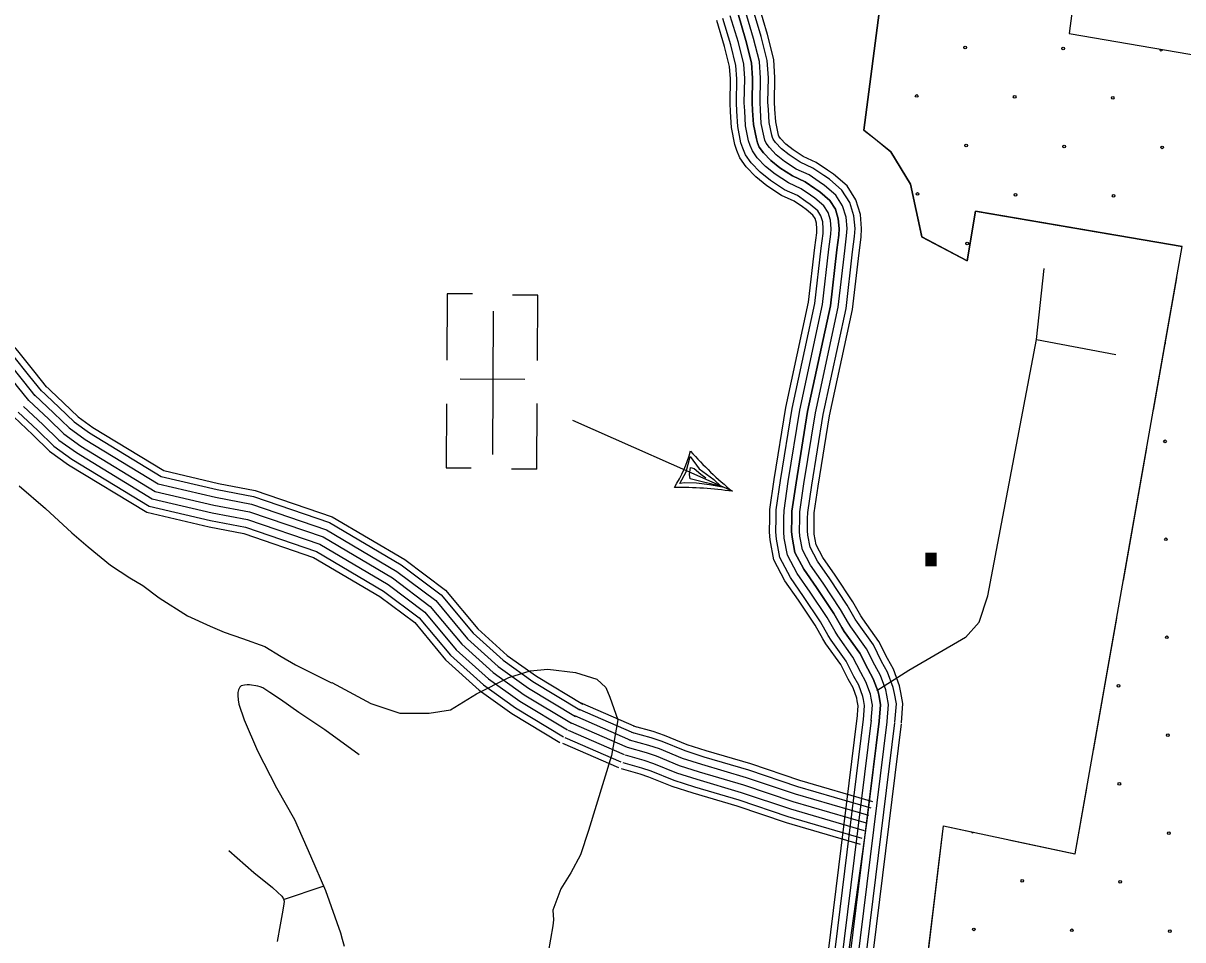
# Model space of a CAD drawing. Extents: x 1788175 to 1969470, y 584502 to 738744.
# Drawn here: x 1805045 to 1809595, y 690385 to 693983 of the extents above; entities that cross this region are included whole.
import ezdxf

# ---------------------------------------------------------------- set-up
doc = ezdxf.new("R2010")
doc.units = 0
for name, color, linetype in [('DESIGN - EROSION CONTROL - Devices', 7, 'Continuous'), ('DESIGN - SCRATCH - User 1', 7, 'Continuous'), ('DESIGN - TRANSPORTATION - Text', 7, 'Continuous'), ('DESIGN - UTILITIES - Cable (Overhead) with Text', 7, 'Continuous'), ('DESIGN - UTILITIES - Cable (Underground) with Text', 7, 'Continuous'), ('SURVEY - CONTOURS - Intermediate with optional Text', 7, 'Continuous'), ('SURVEY - TRANSPORTATION - Roads', 7, 'Continuous'), ('SURVEY - VEGETATION - Features with Text', 7, 'Continuous')]:
    doc.layers.add(name, color=color, linetype=linetype)

msp = doc.modelspace()

# ---------------------------------------------------------------- linework, layer by layer
at = {"layer": 'DESIGN - EROSION CONTROL - Devices'}
for centre in [(1808740.7, 693887.4), (1809125.2, 693883.7), (1808550.3, 693697), (1808934.8, 693693.3), (1809319.4, 693689.5), (1808744.4, 693502.9), (1809129, 693499.1), (1809513.5, 693495.4), (1808554, 693312.5), (1808938.5, 693308.7), (1809323.1, 693305), (1808748.1, 693118.3), (1809524.7, 692341.7), (1809528.4, 691957.2), (1809532.2, 691572.6), (1809341.8, 691382.2), (1809535.9, 691188.1), (1809345.5, 690997.7), (1809539.6, 690803.5), (1808964.7, 690616.8), (1809349.2, 690613.1), (1808774.3, 690426.4), (1809158.8, 690422.7), (1809543.4, 690419)]:
    msp.add_circle(centre, 5.28, dxfattribs=at)
for centre, start, end in [((1809509.8, 693879.9), 159.8346, 0.7167), ((1809521, 692726.3), 322.1065, 17.9018), ((1808770.5, 690811), 196.2684, 319.6043)]:
    msp.add_arc(centre, 5.28, start, end, dxfattribs=at)
at = {"layer": 'DESIGN - SCRATCH - User 1'}
for points in [[(1809592.6, 693105.8), (1808780.6, 693244.9), (1808748.3, 693050.1), (1808570.1, 693144.7), (1808526.5, 693350.3), (1808448.7, 693477.6), (1808342.8, 693563.1), (1808539.5, 695069.6)], [(1809243.5, 694669.1), (1809148.5, 693942.8), (1810462, 693717.7)], [(1808480.1, 689389.2), (1808655, 690833.1), (1809172.5, 690722.5), (1809592.6, 693105.8)]]:
    msp.add_lwpolyline(points, dxfattribs=at)
at = {"layer": 'DESIGN - TRANSPORTATION - Text'}
for points in [[(1805028.2, 692166.4), (1805131.9, 692078.7), (1805235.5, 691983), (1805299.3, 691927.2), (1805387, 691855.5), (1805462.7, 691805.6), (1805514.5, 691775.8), (1805578.3, 691727.9), (1805689.9, 691656.2), (1805777.6, 691616.3), (1805833.4, 691592.4), (1805905.2, 691568.5), (1805992.9, 691536.6), (1806056.6, 691496.7), (1806112.4, 691464.8), (1806176.2, 691433), (1806254.1, 691394)], [(1806255, 691395.8), (1806408.1, 691312.8), (1806523, 691274.5), (1806637.8, 691274.5), (1806720.8, 691287.3), (1806822.8, 691351.1), (1806950.5, 691415), (1807033.4, 691440.5), (1807103.6, 691446.9), (1807212, 691434.1), (1807295, 691408.6), (1807331.3, 691375)], [(1807331.3, 691375), (1807346, 691338.3), (1807377.9, 691248.9), (1807352.4, 691108.5), (1807263.1, 690814.8)], [(1807263.1, 690814.8), (1807231.2, 690719), (1807192.9, 690648.7), (1807154.6, 690584.9), (1807122.7, 690501.9), (1807125.1, 690464.3), (1807122.1, 690439.9), (1807103.9, 690336), (1807073.8, 690240.1), (1807055.5, 690096.3), (1807043.5, 690048.4), (1807035.3, 689956.5), (1807051.1, 689854.5), (1807074.9, 689722.6), (1807098.8, 689648.7), (1807128.6, 689522.8)]]:
    msp.add_lwpolyline(points, dxfattribs=at)
at = {"layer": 'DESIGN - UTILITIES - Cable (Overhead) with Text'}
for p, q in [((1807827.3, 692145.5), (1807201.8, 692422.9)), ((1807645.4, 692221.7), (1807662, 692282.6)), ((1807662, 692282.6), (1807696.9, 692233.5)), ((1807659.5, 692211.8), (1807663.5, 692239.1)), ((1807663.5, 692239.1), (1807677.9, 692235)), ((1807677.9, 692235), (1807703.1, 692213.4)), ((1807696.9, 692233.5), (1807753.9, 692192.1)), ((1807620.4, 692175.9), (1807645.4, 692221.7)), ((1807641.2, 692178.3), (1807620.4, 692175.9)), ((1807685.8, 692177.1), (1807641.2, 692178.3)), ((1807661.2, 692194.9), (1807659.5, 692211.8)), ((1807783.1, 692164), (1807661.2, 692194.9)), ((1807703.1, 692213.4), (1807722.8, 692197.8)), ((1807753.9, 692192.1), (1807783.1, 692164)), ((1807737.8, 692171.4), (1807685.8, 692177.1)), ((1807795.2, 692159.9), (1807737.8, 692171.4))]:
    msp.add_line(p, q, dxfattribs=at)
for centre, radius, start, end in [((1807150, 692445.9), 532.3, 327.6556, 344.514), ((1808703.5, 693219.9), 1386.4, 221.364, 230.8026), ((1807607.8, 690608.8), 1552.3, 81.8723, 90.3001)]:
    msp.add_arc(centre, radius, start, end, dxfattribs=at)
at = {"layer": 'DESIGN - UTILITIES - Cable (Underground) with Text'}
for p, q in [((1806707.8, 692921), (1806706.5, 692660.2)), ((1806807.5, 692920.5), (1806708.5, 692921)), ((1807064.2, 692915.3), (1806964.4, 692915.8)), ((1807062.8, 692658.5), (1807064.1, 692915.3)), ((1807012.4, 692584.4), (1806758.8, 692585.7)), ((1806705.7, 692489.3), (1806704.4, 692237.8)), ((1807060.6, 692232.1), (1807061.9, 692490.1)), ((1806704.5, 692237.8), (1806802.8, 692237.3)), ((1807060.4, 692232.1), (1806961, 692232.6))]:
    msp.add_line(p, q, dxfattribs=at)
msp.add_lwpolyline([(1806888.4, 692852.7), (1806885.6, 692289.7)], dxfattribs=at)
at = {"layer": 'SURVEY - CONTOURS - Intermediate with optional Text'}
for points in [[(1808465.1, 691239.3), (1808470.6, 691310.9), (1808463.5, 691351.6), (1808458.6, 691375.1), (1808436, 691436.3), (1808412.9, 691477.5), (1808380.3, 691542.8), (1808317.8, 691630.7), (1808309.4, 691643.8), (1808278, 691698.6), (1808209.1, 691802.5), (1808160.7, 691871.8), (1808131.8, 691926.4), (1808123, 691974), (1808121.8, 691989.9), (1808122.4, 692039), (1808122.8, 692062.8), (1808138.6, 692169.5), (1808183.2, 692447.2), (1808273.2, 692863), (1808298.6, 693085.1), (1808306.3, 693145.1), (1808308.4, 693177.1), (1808304, 693226.9), (1808288.1, 693278.6), (1808257.3, 693327.6), (1808208, 693370.1), (1808185.8, 693385.3), (1808143.4, 693414.2), (1808092.6, 693437.4), (1808050.1, 693465.5), (1808020, 693489.5), (1807996.5, 693514.2), (1807987.3, 693526.9), (1807984.3, 693534.2), (1807981.4, 693543.6), (1807971.6, 693592.4), (1807968.7, 693644.1), (1807966.9, 693672.4), (1807968.5, 693768), (1807963.8, 693836.5), (1807940.4, 693930.9), (1807906.3, 694044.5)], [(1808490.7, 691237.4), (1808496.4, 691312.2), (1808488.8, 691356.4), (1808483.4, 691382.2), (1808459.5, 691447.1), (1808435.6, 691489.6), (1808402.4, 691556.1), (1808339.2, 691645.1), (1808331.4, 691657.2), (1808299.9, 691712.2), (1808230.4, 691817), (1808182.7, 691885.2), (1808156.4, 691935), (1808148.5, 691977.3), (1808147.5, 691990.7), (1808148.2, 692038.6), (1808148.5, 692060.8), (1808164, 692165.6), (1808208.5, 692442.4), (1808298.6, 692858.8), (1808324.1, 693082), (1808331.9, 693142.7), (1808334.1, 693177.4), (1808329.4, 693231.9), (1808311.7, 693289.4), (1808277, 693344.6), (1808223.7, 693390.6), (1808200.3, 693406.5), (1808156.1, 693436.6), (1808105.1, 693460), (1808065.2, 693486.3), (1808037.4, 693508.5), (1808016.4, 693530.6), (1808009.9, 693539.6), (1808008.5, 693543), (1808006.3, 693549.9), (1807997.2, 693595.6), (1807994.3, 693645.6), (1807992.7, 693673), (1807994.3, 693768.7), (1807989.3, 693840.5), (1807965.2, 693937.7), (1807930.5, 694053.5)], [(1808341.4, 691248.8), (1808345.7, 691305), (1808341.7, 691328.4), (1808339.1, 691340.9), (1808323.1, 691384.2), (1808303.3, 691419.4), (1808273.7, 691478.8), (1808215, 691561.3), (1808203.4, 691579.5), (1808172.4, 691633.4), (1808106.6, 691732.7), (1808054.6, 691807.1), (1808013.4, 691885.2), (1807999.9, 691957.9), (1807997.7, 691986), (1807998.5, 692040.7), (1807998.9, 692072.8), (1808016.1, 692188.5), (1808061.3, 692470.2), (1808150.7, 692883.2), (1808175.5, 693100.1), (1808182.8, 693157), (1808184, 693175.7), (1808181.6, 693203), (1808174.4, 693226.5), (1808162.2, 693245.9), (1808132.3, 693271.6), (1808116, 693282.8), (1808082.2, 693305.8), (1808032.3, 693328.7), (1807977.1, 693365), (1807936, 693397.9), (1807900.8, 693434.9), (1807878.5, 693465.9), (1807867.6, 693491.8), (1807861, 693513.1), (1807848.3, 693576.6), (1807844.9, 693636.8), (1807842.9, 693669.7), (1807844.5, 693764.7), (1807840.8, 693817.2), (1807820.8, 693898.2), (1807789.9, 694001.2)], [(1808372.3, 691246.4), (1808376.9, 691306.5), (1808372.1, 691334.2), (1808369, 691349.5), (1808351.3, 691397.2), (1808330.7, 691434), (1808300.3, 691494.8), (1808240.7, 691578.7), (1808229.9, 691595.6), (1808198.8, 691649.7), (1808132.3, 691750.1), (1808081.1, 691823.2), (1808043, 691895.5), (1808030.6, 691961.9), (1808028.7, 691986.9), (1808029.5, 692040.3), (1808029.9, 692070.3), (1808046.7, 692183.7), (1808091.8, 692464.4), (1808181.4, 692878.2), (1808206.2, 693096.3), (1808213.7, 693154.1), (1808215.1, 693176), (1808212.2, 693209), (1808202.8, 693239.5), (1808186, 693266.3), (1808151.2, 693296.3), (1808133.4, 693308.4), (1808097.5, 693332.9), (1808047.4, 693355.9), (1807995.4, 693390.1), (1807957, 693420.8), (1807924.8, 693454.7), (1807905.7, 693481.1), (1807896.7, 693502.4), (1807891.1, 693520.7), (1807879.2, 693580.5), (1807875.8, 693638.6), (1807873.9, 693670.4), (1807875.5, 693765.5), (1807871.5, 693822), (1807850.7, 693906.4), (1807819, 694012.1)], [(1807848.1, 694022.9), (1807880.6, 693914.5), (1807902.3, 693826.9), (1807906.5, 693766.3), (1807904.9, 693671), (1807906.8, 693640.4), (1807910, 693584.5), (1807921.2, 693528.4), (1807925.9, 693513), (1807932.9, 693496.4), (1807948.7, 693474.5), (1807978, 693443.7), (1808013.6, 693415.2), (1808062.5, 693383), (1808112.8, 693360), (1808150.9, 693334), (1808170.1, 693320.9), (1808209.7, 693286.8), (1808231.2, 693252.5), (1808242.8, 693215), (1808246.2, 693176.4), (1808244.6, 693151.1), (1808237, 693092.6), (1808212, 692873.1), (1808122.3, 692458.7), (1808077.4, 692179), (1808060.8, 692067.8), (1808060.5, 692039.9), (1808059.7, 691987.9), (1808061.4, 691965.9), (1808072.6, 691905.8), (1808107.6, 691839.4), (1808157.9, 691767.6), (1808225.2, 691666), (1808256.4, 691611.7), (1808266.4, 691596), (1808327, 691510.8), (1808358.1, 691448.5), (1808379.6, 691410.2), (1808398.8, 691358), (1808402.6, 691340), (1808408.1, 691307.9), (1808403.3, 691244.1)], [(1808403.3, 691244.1), (1808408.1, 691307.9), (1808402.6, 691340), (1808398.8, 691358), (1808379.6, 691410.2), (1808358.1, 691448.5), (1808327, 691510.8), (1808266.4, 691596), (1808256.4, 691611.7), (1808225.2, 691666), (1808157.9, 691767.6), (1808107.6, 691839.4), (1808072.6, 691905.8), (1808061.4, 691965.9), (1808059.7, 691987.9), (1808060.5, 692039.9), (1808060.8, 692067.8), (1808077.4, 692179), (1808122.3, 692458.7), (1808212, 692873.1), (1808237, 693092.6), (1808244.6, 693151.1), (1808246.2, 693176.4), (1808242.8, 693215), (1808231.2, 693252.5), (1808209.7, 693286.8), (1808170.1, 693320.9), (1808150.9, 693334), (1808112.8, 693360), (1808062.5, 693383), (1808013.6, 693415.2), (1807978, 693443.7), (1807948.7, 693474.5), (1807932.9, 693496.4), (1807925.9, 693513), (1807921.2, 693528.4), (1807910, 693584.5), (1807906.8, 693640.4), (1807904.9, 693671), (1807906.5, 693766.3), (1807902.3, 693826.9), (1807880.6, 693914.5), (1807848.1, 694022.9)], [(1808434.2, 691241.7), (1808439.4, 691309.4), (1808433, 691345.8), (1808428.7, 691366.6), (1808407.8, 691423.3), (1808385.5, 691463), (1808353.7, 691526.8), (1808292.1, 691613.4), (1808282.9, 691627.8), (1808251.6, 691682.3), (1808183.5, 691785), (1808134.2, 691855.6), (1808102.2, 691916.1), (1808092.2, 691970), (1808090.7, 691988.9), (1808091.5, 692039.4), (1808091.8, 692065.3), (1808108, 692174.3), (1808152.7, 692452.9), (1808242.6, 692868.1), (1808267.8, 693088.9), (1808275.4, 693148.1), (1808277.3, 693176.8), (1808273.4, 693221), (1808259.7, 693265.5), (1808233.5, 693307.2), (1808189.1, 693345.5), (1808168.3, 693359.6), (1808128.1, 693387.1), (1808077.5, 693410.2), (1808031.8, 693440.3), (1807999, 693466.6), (1807972.6, 693494.4), (1807960.1, 693511.7), (1807955.1, 693523.6), (1807951.3, 693536), (1807940.8, 693588.4), (1807937.7, 693642.3), (1807935.9, 693671.7), (1807937.5, 693767.2), (1807933, 693831.7), (1807910.5, 693922.7), (1807877.2, 694033.7)], [(1808316.8, 691250.7), (1808320.9, 691303.8), (1808317.4, 691323.8), (1808315.3, 691334.1), (1808300.6, 691373.8), (1808281.5, 691407.9), (1808252.4, 691466.1), (1808194.5, 691547.5), (1808182.3, 691566.7), (1808151.4, 691620.4), (1808086.2, 691718.8), (1808033.5, 691794.2), (1807989.7, 691877), (1807975.3, 691954.6), (1807973, 691985.2), (1807973.7, 692041.1), (1807974.2, 692074.8), (1807991.7, 692192.2), (1808037, 692474.7), (1808126.3, 692887.2), (1808150.9, 693103), (1808158.2, 693159.4), (1808159.2, 693175.4), (1808157.2, 693198.3), (1808151.7, 693216.1), (1808143.2, 693229.6), (1808117.2, 693252), (1808102, 693262.4), (1808070, 693284.2), (1808020.3, 693307), (1807962.6, 693345), (1807919.2, 693379.6), (1807881.8, 693419.1), (1807856.8, 693453.7), (1807844.3, 693483.4), (1807837, 693507), (1807823.8, 693573.4), (1807820.2, 693635.3), (1807818.2, 693669.2), (1807819.7, 693764), (1807816.3, 693813.3), (1807796.9, 693891.7), (1807766.6, 693992.6)], [(1805091.6, 692520.5), (1805047, 692576.8), (1804980.4, 692660), (1804909.3, 692740.7), (1804879.4, 692776.2), (1804853, 692805.6), (1804808.3, 692836.6), (1804773.5, 692855.1), (1804701, 692899.9), (1804641.4, 692943.5), (1804603.9, 692971.8), (1804525.1, 693047.9), (1804491.9, 693087.8), (1804288.2, 693369.9)], [(1805115.9, 692539.8), (1805071.3, 692596.1), (1805004.2, 692680), (1804932.8, 692760.9), (1804902.8, 692796.6), (1804873.7, 692829), (1804824.4, 692863.2), (1804788.9, 692882), (1804718.4, 692925.6), (1804659.9, 692968.3), (1804624.1, 692995.4), (1804547.9, 693069), (1804516.4, 693106.8), (1804313.3, 693388)], [(1805136.1, 692555.8), (1805091.4, 692612.1), (1805023.9, 692696.5), (1804952.3, 692777.7), (1804922.2, 692813.4), (1804890.8, 692848.4), (1804837.8, 692885.2), (1804801.7, 692904.3), (1804732.7, 692947), (1804675.2, 692989), (1804640.8, 693015), (1804566.8, 693086.6), (1804536.7, 693122.6), (1804334.2, 693403.1)], [(1805067.3, 692501.3), (1805022.8, 692557.5), (1804956.7, 692640.1), (1804885.9, 692720.4), (1804856, 692755.8), (1804832.4, 692782.2), (1804792.1, 692810.1), (1804758, 692828.2), (1804683.7, 692874.2), (1804622.9, 692918.6), (1804583.7, 692948.2), (1804502.4, 693026.8), (1804467.4, 693068.8), (1804263.1, 693351.7)], [(1805067.3, 692501.3), (1805022.8, 692557.5), (1804956.7, 692640.1), (1804885.9, 692720.4), (1804856, 692755.8), (1804832.4, 692782.2), (1804792.1, 692810.1), (1804758, 692828.2), (1804683.7, 692874.2), (1804622.9, 692918.6), (1804583.7, 692948.2), (1804502.4, 693026.8), (1804467.4, 693068.8), (1804263.1, 693351.7)], [(1805109.7, 692546.5), (1805186.1, 692475.1), (1805244.4, 692418.3), (1805304.7, 692374.8), (1805586.4, 692203.5), (1805805.9, 692152.5), (1805948.2, 692125.1), (1806247.1, 692023.1), (1806527.8, 691857.2), (1806684.8, 691739.3), (1806810.3, 691588.6), (1806928.1, 691482.5), (1807044.7, 691399.1), (1807228.1, 691288.5)], [(1805126.6, 692564.6), (1805203.2, 692492.9), (1805260.4, 692437.3), (1805318.3, 692395.4), (1805595.9, 692226.7), (1805811.1, 692176.6), (1805954.6, 692149), (1806257.5, 692045.7), (1806541.5, 691877.8), (1806701.9, 691757.4), (1806828.1, 691605.8), (1806943.6, 691501.8), (1807058.3, 691419.8), (1807240.9, 691309.7)], [(1805067.3, 692501.3), (1805143.3, 692430.2), (1805204.4, 692370.7), (1805270.3, 692323.1), (1805562.7, 692145.4), (1805793, 692091.8), (1805932.3, 692065), (1806221.1, 691966.5), (1806493.3, 691805.5), (1806641.7, 691694.1), (1806765.5, 691545.5), (1806889.2, 691434.1), (1807010.6, 691347.3), (1807196.1, 691235.4)], [(1805067.3, 692501.3), (1805143.3, 692430.2), (1805204.4, 692370.7), (1805270.3, 692323.1), (1805562.7, 692145.4), (1805793, 692091.8), (1805932.3, 692065), (1806221.1, 691966.5), (1806493.3, 691805.5), (1806641.7, 691694.1), (1806765.5, 691545.5), (1806889.2, 691434.1), (1807010.6, 691347.3), (1807196.1, 691235.4)], [(1805088.5, 692523.9), (1805164.7, 692452.6), (1805224.4, 692394.5), (1805287.5, 692348.9), (1805574.6, 692174.5), (1805799.5, 692122.1), (1805940.3, 692095), (1806234.1, 691994.8), (1806510.5, 691831.4), (1806663.3, 691716.7), (1806787.9, 691567.1), (1806908.6, 691458.3), (1807027.7, 691373.2), (1807212.1, 691262)], [(1805025, 692456), (1805100.5, 692385.4), (1805164.4, 692323.1), (1805236, 692271.4), (1805539, 692087.3), (1805780.1, 692031.1), (1805916.4, 692004.9), (1806195, 691909.9), (1806458.8, 691753.9), (1806598.7, 691648.9), (1806720.7, 691502.4), (1806850.3, 691385.7), (1806976.5, 691295.4), (1807164.1, 691182.3)], [(1805046.2, 692478.6), (1805121.9, 692407.8), (1805184.4, 692346.9), (1805253.2, 692297.2), (1805550.8, 692116.3), (1805786.6, 692061.5), (1805924.3, 692035), (1806208, 691938.2), (1806476, 691779.7), (1806620.2, 691671.5), (1806743.1, 691524), (1806869.7, 691409.9), (1806993.6, 691321.4), (1807180.1, 691208.9)], [(1805007.4, 692437.2), (1805082.7, 692366.8), (1805147.8, 692303.4), (1805221.8, 692249.9), (1805529.1, 692063.2), (1805774.8, 692006), (1805909.7, 691980), (1806184.2, 691886.4), (1806444.5, 691732.5), (1806580.9, 691630.1), (1806702.1, 691484.5), (1806834.2, 691365.6), (1806962.4, 691273.9), (1807150.8, 691160.3)], [(1807450.9, 691220), (1807231.1, 691315.8)], [(1807440.6, 691196.4), (1807220.9, 691292.3)], [(1807415.8, 691139.6), (1807196.1, 691235.4)], [(1807415.8, 691139.6), (1807196.1, 691235.4)], [(1807428.2, 691168), (1807208.5, 691263.8)], [(1808378.4, 690927.3), (1808091.6, 691010.8), (1807899.1, 691075.7), (1807724, 691127.4), (1807650.4, 691150.8), (1807560.8, 691187.7), (1807516.4, 691202.7), (1807439.3, 691224.1)], [(1808058.3, 689150.5), (1808317.2, 691254.7)], [(1808086.1, 689173.8), (1808341.7, 691251.6)], [(1808120.9, 689203), (1808372.5, 691247.9)], [(1808403.3, 691244.1), (1808353.9, 690843), (1808125.1, 689204.8)], [(1808153.7, 689215.5), (1808403.3, 691244.1)], [(1808186.4, 689227.8), (1808434, 691240.3)], [(1808219.2, 689240), (1808464.8, 691236.5)], [(1808246.3, 689250.2), (1808490.3, 691233.4)], [(1807391, 691082.8), (1807171.3, 691178.6)], [(1807403.4, 691111.2), (1807183.7, 691207)], [(1808371.3, 690902.6), (1808083.8, 690986.2), (1807891.3, 691051.1), (1807716.4, 691102.8), (1807641.6, 691126.7), (1807551.8, 691163.6), (1807508.9, 691178.1), (1807432.4, 691199.4)], [(1807381.1, 691060.1), (1807161.4, 691155.9)], [(1808353.9, 690843), (1808065.3, 690927.1), (1807872.7, 690992), (1807698.2, 691043.5), (1807620.3, 691068.4), (1807530, 691105.5), (1807490.6, 691118.8), (1807415.8, 691139.6)], [(1808353.9, 690843), (1808065.3, 690927.1), (1807872.7, 690992), (1807698.2, 691043.5), (1807620.3, 691068.4), (1807530, 691105.5), (1807490.6, 691118.8), (1807415.8, 691139.6)], [(1808362.6, 690872.8), (1808074.6, 690956.7), (1807882, 691021.6), (1807707.3, 691073.1), (1807631, 691097.5), (1807540.9, 691134.6), (1807499.8, 691148.5), (1807424.1, 691169.5)], [(1808345.3, 690813.3), (1808056, 690897.5), (1807863.3, 690962.4), (1807689.1, 691013.9), (1807609.7, 691039.2), (1807519.1, 691076.5), (1807481.5, 691089.2), (1807407.5, 691109.7)], [(1808329.7, 690759.8), (1808039.3, 690844.3), (1807846.5, 690909.3), (1807672.7, 690960.6), (1807590.6, 690986.8), (1807499.6, 691024.3), (1807465.1, 691035.9), (1807392.6, 691056.1)], [(1808336.6, 690783.5), (1808046.7, 690867.9), (1807854, 690932.9), (1807680, 690984.2), (1807599.1, 691010.1), (1807508.3, 691047.4), (1807472.4, 691059.5), (1807399.2, 691079.9)]]:
    msp.add_lwpolyline(points, dxfattribs=at)
at = {"layer": 'SURVEY - TRANSPORTATION - Roads'}
for points in [[(1809020.6, 692740.9), (1809050.1, 693020.1)], [(1808741.5, 691571.4), (1808796.1, 691631.4), (1808829.2, 691735.5), (1809020.6, 692740.9)], [(1809020.6, 692740.9), (1809331.8, 692682.9)], [(1808741.5, 691571.4), (1808519.2, 691442.1), (1808393.8, 691362.4)], [(1806363.5, 691111.5), (1806228.6, 691209.6), (1806126.2, 691277), (1806054.5, 691328.6), (1806012.4, 691355.5), (1805985.3, 691373.8), (1805974.8, 691378.5), (1805965.9, 691381), (1805933, 691386), (1805923.3, 691385.8), (1805913.5, 691385.1), (1805900.3, 691381.5), (1805895.2, 691376.3), (1805892.5, 691371.5), (1805889.9, 691366.7), (1805886.8, 691356.2), (1805886.4, 691344.1), (1805888.2, 691327.7), (1805890.8, 691310), (1805911.1, 691248.2), (1805964.1, 691127.3), (1806038.8, 690982.1), (1806109.2, 690857.8), (1806171.8, 690715), (1806231.4, 690578.3), (1806289, 690412.2), (1806296, 690387.7), (1806304, 690360.6)], [(1805851.8, 690735.7), (1805949.4, 690649.6), (1806022.9, 690590.7), (1806042.6, 690572.1), (1806058.8, 690556.8), (1806066.4, 690545.9), (1806068, 690536.7), (1806067.6, 690524.9), (1806060.6, 690487.7), (1806053.3, 690444.6), (1806041.4, 690379.4)], [(1806066.5, 690543.6), (1806222.2, 690595.7)]]:
    msp.add_lwpolyline(points, dxfattribs=at)
at = {"layer": 'SURVEY - VEGETATION - Features with Text'}
for points in [[(1808539.5, 695069.6), (1808342.5, 693563.2)], [(1808397.9, 693986.8), (1808363.7, 693725.1)], [(1808363.7, 693725.1), (1808342.5, 693563.2)], [(1808342.8, 693563.1), (1808388.3, 693527.9), (1808448.7, 693477.6), (1808526.5, 693350.3), (1808570.1, 693144.7)], [(1808342.8, 693563.1), (1808388.3, 693527.9), (1808448.7, 693477.6), (1808515.3, 693368.5)], [(1808553.2, 693224.4), (1808570.1, 693144.7)], [(1808569.7, 693144.1), (1808748.3, 693050.1), (1808780.6, 693244.9), (1809592.6, 693105.8)], [(1808795.1, 693242.5), (1809055.3, 693197.9)], [(1809055.3, 693197.9), (1809315.5, 693153.3)], [(1808569.7, 693144.1), (1808748.3, 693050.1), (1808758.5, 693111.4)], [(1808476.2, 689337.1), (1808655, 690833.1), (1809172.5, 690722.5), (1809592.6, 693105.8)], [(1809463.4, 693127.9), (1809592.6, 693105.8)], [(1809525.3, 692723.7), (1809571.1, 692983.7)], [(1809479.4, 692463.7), (1809525.3, 692723.7)], [(1809407.6, 692056), (1809453.4, 692316)], [(1809361.8, 691796), (1809407.6, 692056)], [(1809289.9, 691388.3), (1809335.7, 691648.3)], [(1809244.1, 691128.3), (1809289.9, 691388.3)], [(1809170.6, 690722.9), (1809172.5, 690722.5), (1809218, 690980.6)], [(1808637.1, 690683.5), (1808655, 690833.1), (1808765.8, 690809.4)], [(1808912.5, 690778.1), (1809170.6, 690722.9)], [(1808605.8, 690421.4), (1808637.1, 690683.5)]]:
    msp.add_lwpolyline(points, dxfattribs=at)

# ---------------------------------------------------------------- texts
at = {"layer": 'DESIGN - UTILITIES - Cable (Underground) with Text'}
msp.add_text('.', height=343, dxfattribs=at).set_placement((1808542.7, 691851.6))

doc.saveas('drawing.dxf')
